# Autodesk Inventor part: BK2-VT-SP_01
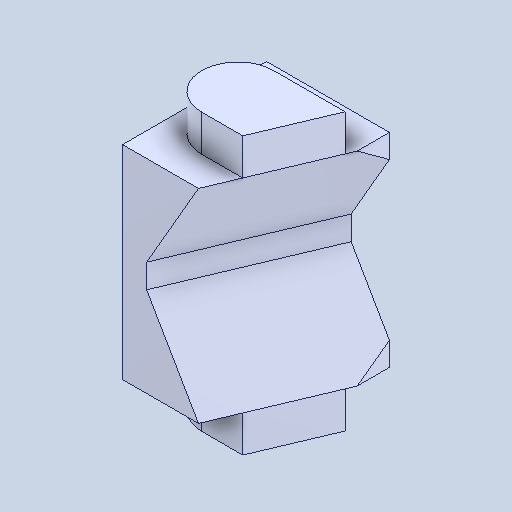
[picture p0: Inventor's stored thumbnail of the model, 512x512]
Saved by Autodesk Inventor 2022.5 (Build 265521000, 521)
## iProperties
Created: 2024-08
Part Number: BK2-VT-SP_01
Material: 一般
Document SubType Name: Modeling
Designer: ImaoCorp
Density: 1 g/cm^3
Appearance: 既定
Author: ImaoCorp
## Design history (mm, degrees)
feature "BK2-VT-SP_01"
node "ソリッド1"
